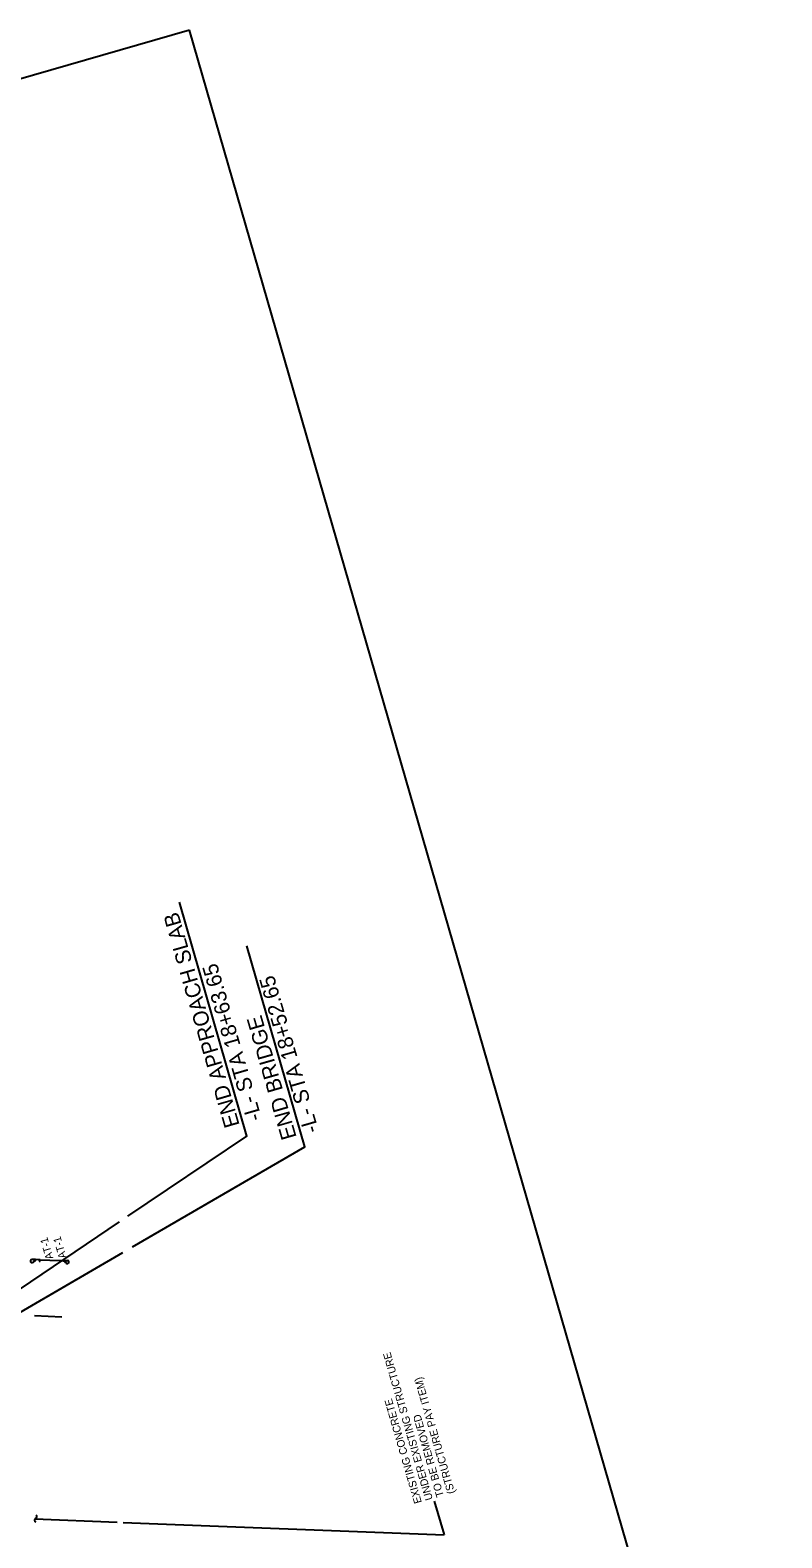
# Model space of a CAD drawing. Extents: x 2167182 to 2168576, y 842635 to 844493.
# Drawn here: x 2168088 to 2168576, y 843360 to 844341 of the extents above; entities that cross this region are included whole.
import ezdxf

# ---------------------------------------------------------------- set-up
doc = ezdxf.new("R2010")
doc.units = 0
for name, color, linetype in [('Default', 7, 'Continuous'), ('Old_Level_2', 7, 'Continuous'), ('Prop Dimension', 7, 'Continuous'), ('Prop Dimension Text', 7, 'Continuous'), ('Prop Guardrail', 7, 'Continuous'), ('Prop Guardrail Anchor Unit CELL', 7, 'Continuous'), ('Sheet Layout Plan Border', 7, 'Continuous')]:
    doc.layers.add(name, color=color, linetype=linetype)

msp = doc.modelspace()

# ---------------------------------------------------------------- linework, layer by layer
at = {"layer": 'Default'}
msp.add_lwpolyline([(2168108.41, 843503.97), (2168090.6, 843504.87)], dxfattribs=at)
at = {"layer": 'Prop Dimension'}
for p, q in [((2168350.36, 843384.29), (2168356.71, 843362.32)), ((2168090.88, 843372.68), (2168144.31, 843370.59)), ((2168148.08, 843370.45), (2168356.71, 843362.32))]:
    msp.add_line(p, q, dxfattribs=at)
for points in [[(2168151.32, 843569.58), (2168228.58, 843621.68), (2168184.8, 843773.9)], [(2168154.17, 843549.62), (2168266.28, 843614.77), (2168228.48, 843745.51)], [(2168045.09, 843497.94), (2168145.81, 843565.86)], [(2168046.48, 843487.03), (2168147.89, 843545.97)]]:
    msp.add_lwpolyline(points, dxfattribs=at)
for centre, start, end in [((2168091.81, 843371.84), 111.96887, 248.73324), ((2168090.88, 843374.16), 288.30034, 56.61855)]:
    msp.add_arc(centre, 1.25, start, end, dxfattribs=at)
at = {"layer": 'Prop Guardrail'}
msp.add_line((2168094.21, 843541.23), (2168106.71, 843540.86), dxfattribs=at)
at = {"layer": 'Prop Guardrail Anchor Unit CELL'}
for p, q in [((2168090.67, 843541.34), (2168088.95, 843541.39)), ((2168089.7, 843539.78), (2168090.45, 843540.73)), ((2168090.47, 843541.35), (2168090.45, 843540.54)), ((2168091.17, 843541.33), (2168090.45, 843540.54)), ((2168090.45, 843540.54), (2168091.15, 843540.52)), ((2168090.47, 843541.35), (2168090.46, 843540.99)), ((2168090.47, 843541.35), (2168090.46, 843540.99)), ((2168091.17, 843541.33), (2168090.47, 843541.35)), ((2168090.47, 843541.35), (2168091.15, 843540.52)), ((2168090.6, 843541.34), (2168090.74, 843541.34)), ((2168090.6, 843541.34), (2168090.74, 843541.34)), ((2168094.21, 843541.23), (2168090.67, 843541.34)), ((2168091.15, 843540.52), (2168091.17, 843541.33)), ((2168093.51, 843541.25), (2168093.49, 843540.45)), ((2168094.21, 843541.23), (2168093.49, 843540.45)), ((2168093.49, 843540.45), (2168094.19, 843540.43)), ((2168094.21, 843541.23), (2168093.51, 843541.25)), ((2168093.51, 843541.25), (2168094.19, 843540.43)), ((2168094.19, 843540.43), (2168094.21, 843541.23)), ((2168106.68, 843540.05), (2168106.71, 843540.86)), ((2168107.41, 843540.84), (2168106.68, 843540.05)), ((2168107.38, 843540.03), (2168106.68, 843540.05)), ((2168106.71, 843540.86), (2168110.25, 843540.75)), ((2168106.71, 843540.86), (2168107.41, 843540.84)), ((2168106.71, 843540.86), (2168107.38, 843540.03)), ((2168107.41, 843540.84), (2168107.38, 843540.03)), ((2168109.79, 843539.96), (2168109.82, 843540.76)), ((2168110.52, 843540.74), (2168109.79, 843539.96)), ((2168110.49, 843539.94), (2168109.79, 843539.96)), ((2168109.82, 843540.76), (2168110.52, 843540.74)), ((2168109.82, 843540.76), (2168110.49, 843539.94)), ((2168110.38, 843540.75), (2168110.25, 843540.75)), ((2168110.25, 843540.75), (2168111.97, 843540.7)), ((2168110.38, 843540.75), (2168110.25, 843540.75)), ((2168110.52, 843540.74), (2168110.49, 843539.94)), ((2168111.13, 843539.14), (2168110.49, 843540.04)), ((2168110.52, 843540.74), (2168110.5, 843540.39)), ((2168110.52, 843540.74), (2168110.5, 843540.39))]:
    msp.add_line(p, q, dxfattribs=at)
for centre, major_axis, start_param, end_param in [((2168088.92, 843540.4), (-0.03, -0.993), 3.141593, 7.214552), ((2168111.94, 843539.71), (0.03, 0.993), 2.210226, 6.283185)]:
    msp.add_ellipse(centre, major_axis=major_axis, ratio=0.995379, start_param=start_param, end_param=end_param, dxfattribs=at)
at = {"layer": 'Sheet Layout Plan Border'}
msp.add_lwpolyline([(2168191.21, 844341.01), (2167182.42, 844049.75), (2167182.42, 844049.75), (2167567.43, 842716.21), (2168576.23, 843007.46)], close=True, dxfattribs=at)

# ---------------------------------------------------------------- texts
at = {"layer": 'Old_Level_2'}
for s, p in [('END APPROACH SLAB', (2168223.99, 843628.86)), ('-L- STA 18+63.65', (2168238.4, 843633.03)), ('-L- STA 18+52.65', (2168275.42, 843625.18)), ('END BRIDGE', (2168261.01, 843621.02))]:
    msp.add_text(s, height=10, rotation=106.12627, dxfattribs=at).set_placement(p)
at = {"layer": 'Prop Dimension Text'}
for s, p in [('UNDER EXISTING STRUCTURE', (2168349.51, 843385.58)), ('(STRUCTURE PAY ITEM)', (2168363.92, 843389.74)), ('EXISTING CONCRETE', (2168342.3, 843383.5)), ('TO BE REMOVED', (2168356.71, 843387.66))]:
    msp.add_text(s, height=5, rotation=106.1042, dxfattribs=at).set_placement(p)
at = {"layer": 'Prop Guardrail Anchor Unit CELL'}
for p in [(2168102.91, 843542.3), (2168111.41, 843542.91)]:
    msp.add_text('AT-1', height=5, rotation=106.18713, dxfattribs=at).set_placement(p)

doc.saveas('drawing.dxf')
